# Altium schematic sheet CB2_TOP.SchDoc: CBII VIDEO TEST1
size A2; Engineer: SHOWELL; DocumentNumber: 1; Revision: 1.00; SheetNumber: 1; SheetTotal: 1; PageSetup: Record=PageOptions|CenterHorizontal=True|CenterVertical=True|PrintScale=1.47|XCorrection=1.00|YCorrection=1.00|PrintKind=0|BorderSize=5000000|LeftOffset=0|BottomOffset=0|Orientation=2|PaperLength=1000|PaperWidth=1000|Scale=100|PaperSource=7|PrintQuality=-4|MediaType=1|DitherType=10|PaperKind=A2|PrintScaleMode=1
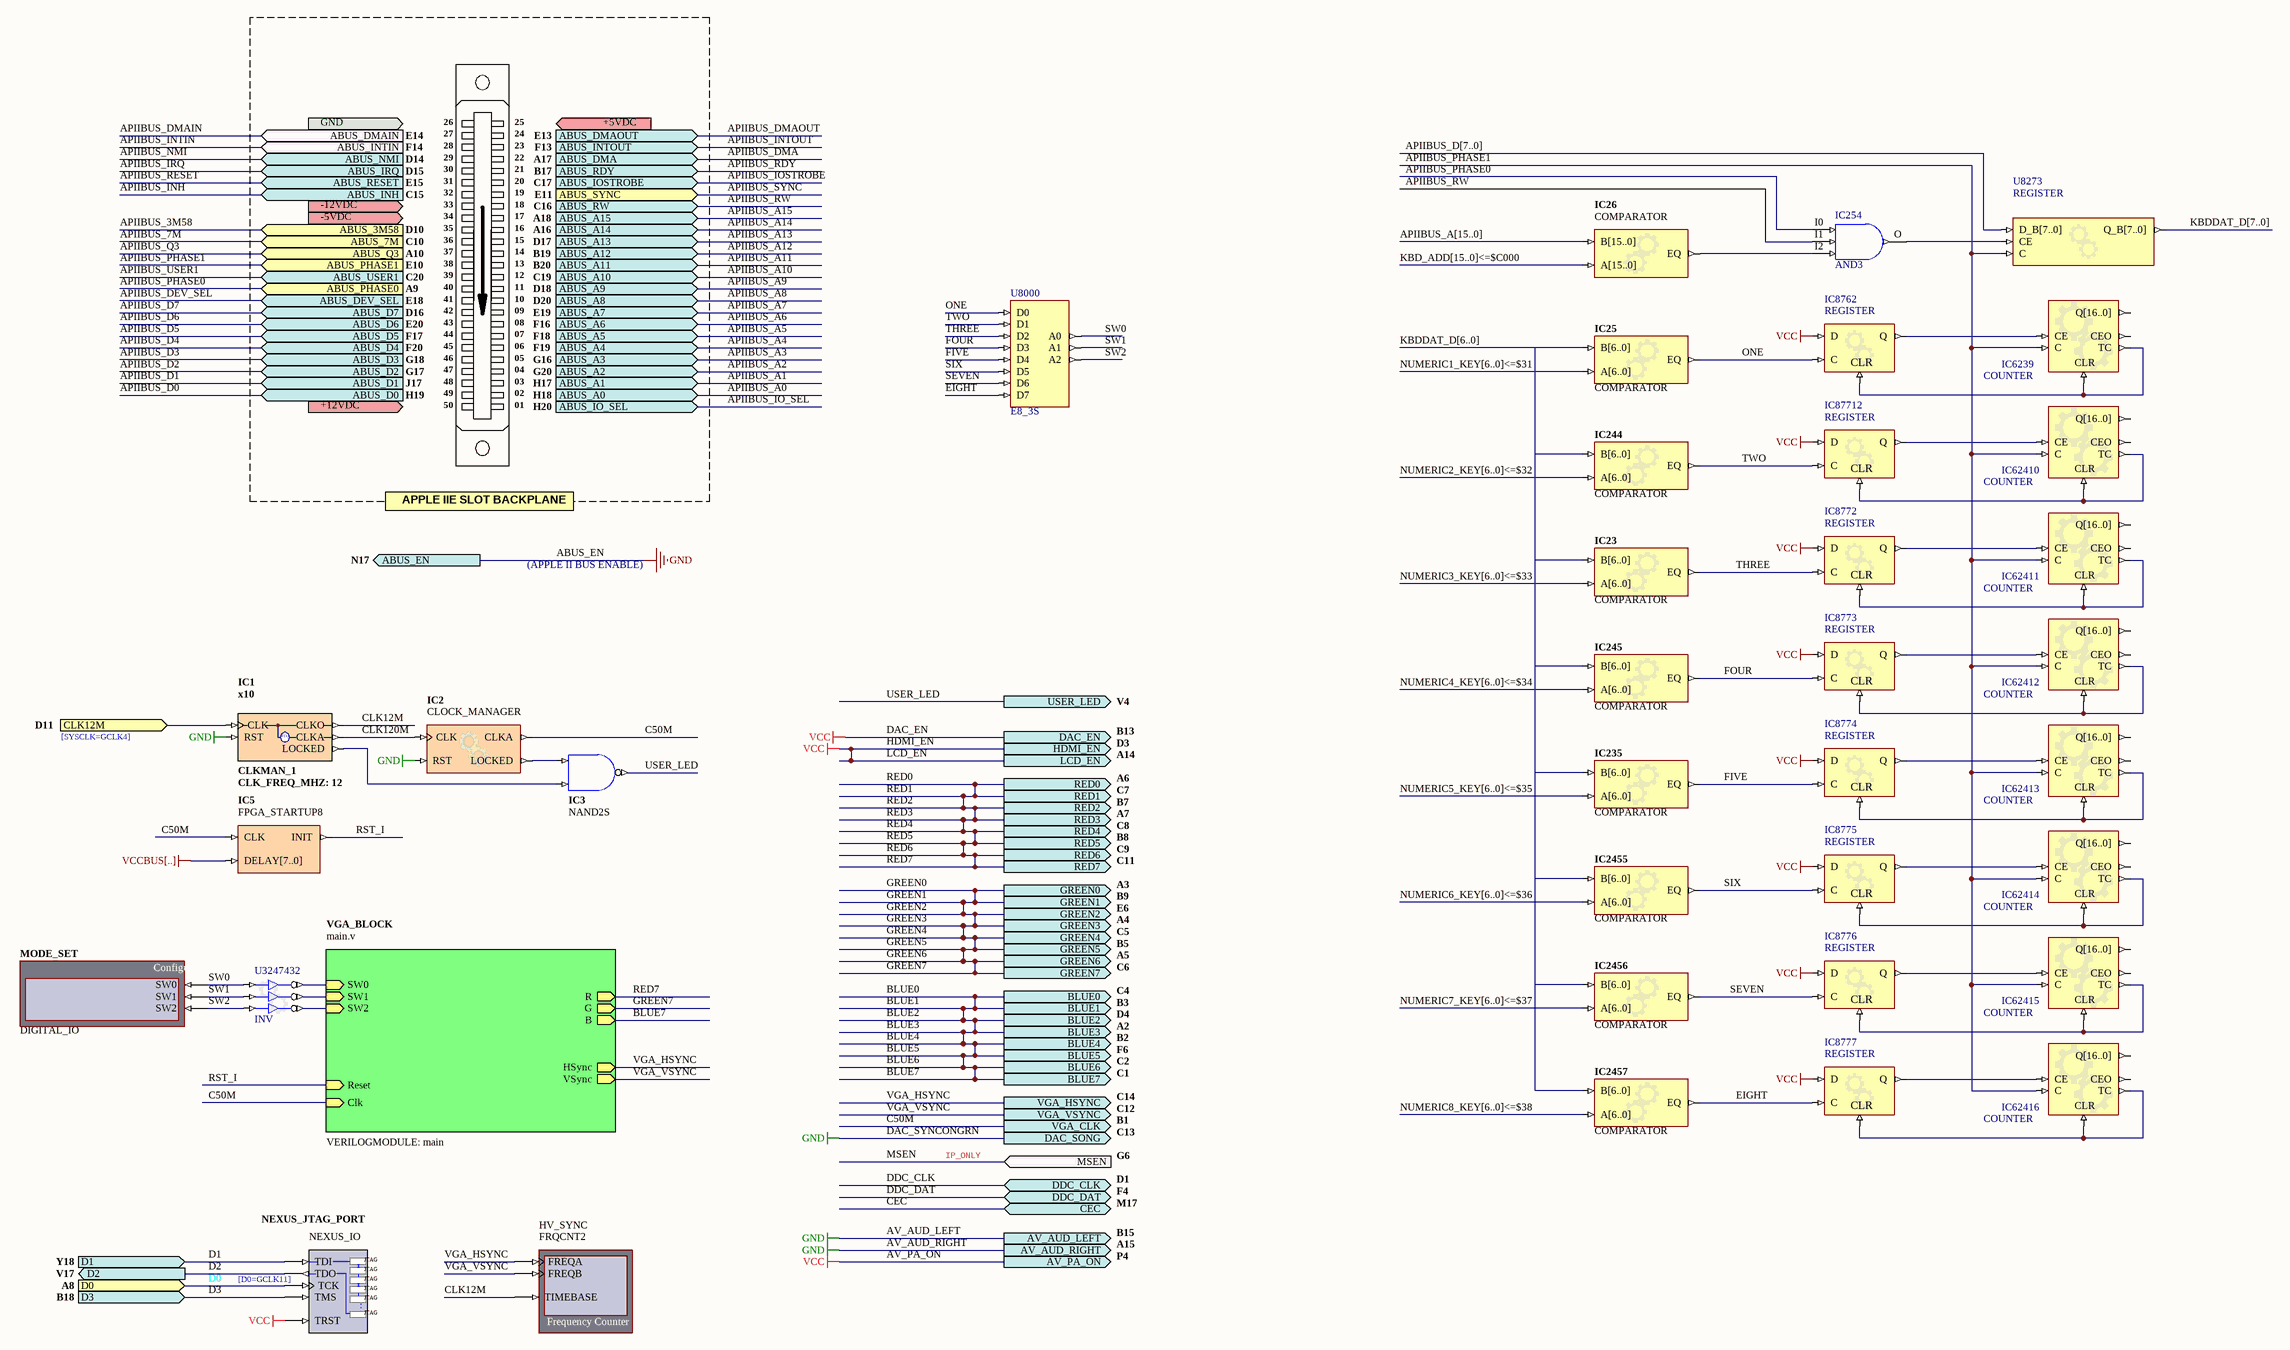
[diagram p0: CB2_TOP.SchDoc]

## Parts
HV_SYNC  FRQCNT2
IC1  CLKMAN_1  CLK_FREQ_MHZ: 12  ClkA_Operation: x10
IC2  CLOCK_MANAGER
IC3  NAND2S
IC5  FPGA_STARTUP8
IC23  COMPARATOR
IC25  COMPARATOR
IC26  COMPARATOR
IC235  COMPARATOR
IC244  COMPARATOR
IC245  COMPARATOR
IC254  AND3
IC2455  COMPARATOR
IC2456  COMPARATOR
IC2457  COMPARATOR
IC6239  COUNTER
IC8762  REGISTER
IC8772  REGISTER
IC8773  REGISTER
IC8774  REGISTER
IC8775  REGISTER
IC8776  REGISTER
IC8777  REGISTER
IC62410  COUNTER
IC62411  COUNTER
IC62412  COUNTER
IC62413  COUNTER
IC62414  COUNTER
IC62415  COUNTER
IC62416  COUNTER
IC87712  REGISTER
MODE_SET  DIGITAL_IO
NEXUS_JTAG_PORT  NEXUS_IO
U8000  E8_3S
U8273  REGISTER
U3247432  INV

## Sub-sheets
VGA_BLOCK = main.v: B (out), Clk (in), G (out), HSync (out), R (out), Reset (in), SW0 (in), SW1 (in), SW2 (in), VSync (out)  | VERILOGMODULE: main

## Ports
ABUS_3M58 (in, see D10), ABUS_7M (in, see C10), ABUS_A0 (in, see H18), ABUS_A1 (in, see H17), ABUS_A2 (in, see G20), ABUS_A3 (in, see G16), ABUS_A4 (in, see F19), ABUS_A5 (in, see F18), ABUS_A6 (in, see F16), ABUS_A7 (in, see E19), ABUS_A8 (in, see D20), ABUS_A9 (in, see D18), ABUS_A10 (in, see C19), ABUS_A11 (in, see B20), ABUS_A12 (in, see B19), ABUS_A13 (in, see D17), ABUS_A14 (in, see A16), ABUS_A15 (in, see A18), ABUS_D0 (in, see H19), ABUS_D1 (in, see J17), ABUS_D2 (in, see G17), ABUS_D3 (in, see G18), ABUS_D4 (in, see F20), ABUS_D5 (in, see F17), ABUS_D6 (in, see E20), ABUS_D7 (in, see D16), ABUS_DEV_SEL (in, see E18), ABUS_DMA (in, see A17), ABUS_DMAIN (in, see E14), ABUS_DMAOUT (in, see E13), ABUS_EN (out, see N17), ABUS_INH (in, see C15), ABUS_INTIN (in, see F14), ABUS_INTOUT (in, see F13), ABUS_IO_SEL (in, see H20), ABUS_IOSTROBE (in, see C17), ABUS_IRQ (in, see D15), ABUS_NMI (in, see D14), ABUS_PHASE0 (in, see A9), ABUS_PHASE1 (in, see E10), ABUS_Q3 (in, see A10), ABUS_RDY (in, see B17), ABUS_RESET (in, see E15), ABUS_RW (in, see C16), ABUS_SYNC (in, see E11), ABUS_USER1 (in, see C20), AV_AUD_LEFT (out, see B15), AV_AUD_RIGHT (out, see A15), AV_PA_ON (out, see P4), BLUE0 (out, see C4), BLUE1 (out, see B3), BLUE2 (out, see D4), BLUE3 (out, see A2), BLUE4 (out, see B2), BLUE5 (out, see F6), BLUE6 (out, see C2), BLUE7 (out, see C1), CEC (bidir, see M17), CLK12M (in, see D11), D0 (in, see A8), D1 (in, see Y18), D2 (out, see V17), D3 (in, see B18), DAC_EN (out, see B13), DAC_SONG (out, see C13), DDC_CLK (bidir, see D1), DDC_DAT (bidir, see F4), GREEN0 (out, see A3), GREEN1 (out, see B9), GREEN2 (out, see E6), GREEN3 (out, see A4), GREEN4 (out, see C5), GREEN5 (out, see B5), GREEN6 (out, see A5), GREEN7 (out, see C6), HDMI_EN (out, see D3), LCD_EN (out, see A14), MSEN (in, see G6), RED0 (out, see A6), RED1 (out, see C7), RED2 (out, see B7), RED3 (out, see A7), RED4 (out, see C8), RED5 (out, see B8), RED6 (out, see C9), RED7 (out, see C11), USER_LED (out, see V4), VGA_CLK (out, see B1), VGA_HSYNC (out, see C14), VGA_VSYNC (out, see C12)

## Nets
ABUS_EN: IC1.RST IC2.RST ; port DAC_SONG, port AV_AUD_LEFT, port AV_AUD_RIGHT, port ABUS_EN  [also labelled AV_AUD_LEFT, AV_AUD_RIGHT, DAC_SYNCONGRN, GND]
AV_PA_ON: IC8762.D IC8772.D IC8773.D IC8774.D IC8775.D IC8776.D IC8777.D IC87712.D NEXUS_JTAG_PORT.TRST ; port HDMI_EN, port AV_PA_ON, port DAC_EN, port LCD_EN  [also labelled DAC_EN, HDMI_EN, LCD_EN, VCC]
APIIBUS_PHASE0: IC254.I0 ; port ABUS_PHASE0
APIIBUS_PHASE1: IC6239.C IC62410.C IC62411.C IC62412.C IC62413.C IC62414.C IC62415.C IC62416.C U8273.C ; port ABUS_PHASE1
APIIBUS_RW: IC254.I1 ; port ABUS_RW
BLUE0: port BLUE2, port BLUE3, port BLUE4, port BLUE5, port BLUE6, port BLUE7, port BLUE0, port BLUE1, sheet VGA_BLOCK/B  [also labelled BLUE1, BLUE2, BLUE3, BLUE4, BLUE5, BLUE6, BLUE7]
C50M: IC2.CLKA IC5.CLK ; port VGA_CLK, sheet VGA_BLOCK/Clk
CLK12M: IC1.CLK ; port CLK12M
CLK12M: HV_SYNC.TIMEBASE IC1.CLKO  [a separate net that carries the same name]
CLK120M: IC1.CLKA IC2.CLK
D0: NEXUS_JTAG_PORT.TCK ; port D0
D1: NEXUS_JTAG_PORT.TDI ; port D1
D2: NEXUS_JTAG_PORT.TDO ; port D2
D3: NEXUS_JTAG_PORT.TMS ; port D3
EIGHT: IC2457.EQ IC8777.C U8000.D7
FIVE: IC235.EQ IC8774.C U8000.D4
FOUR: IC245.EQ IC8773.C U8000.D3
GREEN0: port GREEN2, port GREEN3, port GREEN4, port GREEN5, port GREEN6, port GREEN7, port GREEN0, port GREEN1, sheet VGA_BLOCK/G  [also labelled GREEN1, GREEN2, GREEN3, GREEN4, GREEN5, GREEN6, GREEN7]
ONE: IC25.EQ IC8762.C U8000.D0
RED0: port RED2, port RED3, port RED4, port RED5, port RED6, port RED7, port RED0, port RED1, sheet VGA_BLOCK/R  [also labelled RED1, RED2, RED3, RED4, RED5, RED6, RED7]
RST_I: IC5.INIT ; sheet VGA_BLOCK/Reset
SEVEN: IC2456.EQ IC8776.C U8000.D6
SIX: IC2455.EQ IC8775.C U8000.D5
SW0: MODE_SET.SW0 U8000.A0 U3247432.I0
SW1: MODE_SET.SW1 U8000.A1 U3247432.I1
SW2: MODE_SET.SW2 U8000.A2 U3247432.I2
THREE: IC23.EQ IC8772.C U8000.D2
TWO: IC244.EQ IC87712.C U8000.D1
USER_LED: IC3.O ; port USER_LED
VGA_HSYNC: HV_SYNC.FREQA ; port VGA_HSYNC, sheet VGA_BLOCK/HSync
VGA_VSYNC: HV_SYNC.FREQB ; port VGA_VSYNC, sheet VGA_BLOCK/VSync
NetIC1_LOCKED: IC1.LOCKED IC3.I1
NetIC2_LOCKED: IC2.LOCKED IC3.I0
NetIC26_EQ: IC26.EQ IC254.I2
NetIC254_O: IC254.O U8273.CE
NetIC6239_CE: IC6239.CE IC8762.Q
NetIC6239_CLR: IC6239.CLR IC6239.TC IC8762.CLR
NetIC8772_CLR: IC8772.CLR IC62411.CLR IC62411.TC
NetIC8772_Q: IC8772.Q IC62411.CE
NetIC8773_CLR: IC8773.CLR IC62412.CLR IC62412.TC
NetIC8773_Q: IC8773.Q IC62412.CE
NetIC8774_CLR: IC8774.CLR IC62413.CLR IC62413.TC
NetIC8774_Q: IC8774.Q IC62413.CE
NetIC8775_CLR: IC8775.CLR IC62414.CLR IC62414.TC
NetIC8775_Q: IC8775.Q IC62414.CE
NetIC8776_CLR: IC8776.CLR IC62415.CLR IC62415.TC
NetIC8776_Q: IC8776.Q IC62415.CE
NetIC8777_CLR: IC8777.CLR IC62416.CLR IC62416.TC
NetIC8777_Q: IC8777.Q IC62416.CE
NetIC62410_CE: IC62410.CE IC87712.Q
NetIC62410_CLR: IC62410.CLR IC62410.TC IC87712.CLR
NetU3247432_O0: U3247432.O0 ; sheet VGA_BLOCK/SW0
NetU3247432_O1: U3247432.O1 ; sheet VGA_BLOCK/SW1
NetU3247432_O2: U3247432.O2 ; sheet VGA_BLOCK/SW2

Not connected (* = marked no-connect by the designer): IC5 DELAY[7..0]; IC23 A[6..0] B[6..0]; IC25 A[6..0] B[6..0]; IC26 A[15..0] B[15..0]; IC235 A[6..0] B[6..0]; IC244 A[6..0] B[6..0]; IC245 A[6..0] B[6..0]; IC2455 A[6..0] B[6..0]; IC2456 A[6..0] B[6..0]; IC2457 A[6..0] B[6..0]; IC6239 CEO Q[16..0]; IC62410 CEO Q[16..0]; IC62411 CEO Q[16..0]; IC62412 CEO Q[16..0]; IC62413 CEO Q[16..0]; IC62414 CEO Q[16..0]; IC62415 CEO Q[16..0]; IC62416 CEO Q[16..0]; U8273 D_B[7..0] Q_B[7..0]

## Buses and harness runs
bus APIIBUS_A[15..0]
bus APIIBUS_D[7..0]
bus KBD_ADD[15..0]<=$C000
bus KBDDAT_D[6..0]
bus KBDDAT_D[7..0]
bus NUMERIC1_KEY[6..0]<=$31
bus NUMERIC2_KEY[6..0]<=$32
bus NUMERIC3_KEY[6..0]<=$33
bus NUMERIC4_KEY[6..0]<=$34
bus NUMERIC5_KEY[6..0]<=$35
bus NUMERIC6_KEY[6..0]<=$36
bus NUMERIC7_KEY[6..0]<=$37
bus NUMERIC8_KEY[6..0]<=$38

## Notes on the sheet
- GND
- 26
- 27
- 28
- 29
- 30
- 25
- 24
- 23
- 22
- 21
- +5VDC
- -12VDC
- -5VDC
- 31
- 32
- 33
- 34
- 35
- 20
- 19
- 18
- 17
- 16
- 36
- 37
- 38
- 39
- 40
- 15
- 14
- 13
- 12
- 11
- 41
- 42
- 43
- 44
- 45
- 10
- 09
- 08
- 07
- 06
- +12VDC
- 46
- 47
- 48
- 49
- 50
- 05
- 04
- 03
- 02
- 01
- APPLE IIE SLOT BACKPLANE
- (APPLE II BUS ENABLE)
- [SYSCLK=GCLK4]
- IP_ONLY
- (near NEXUS_JTAG_PORT) [D0=GCLK11]
- Labels drawn without touching a wire or pin: VCCBUS[..]

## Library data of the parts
HV_SYNC = FRQCNT2: Frequency Counter; NEXUS_CORE: Instrument; NEXUS_JTAG_DEVICE: True; NEXUS_JTAG_ORDER: 0
IC1 = CLKMAN_1: Single Operational Output Clock Manager; Clk_Count: 1
IC2 = CLOCKMANAGER: Configurable Clock Manager; ConfiguratorName: GENERIC_CLOCKMANAGER; ConfigurationParameters: {}Version[1.0]{}Option_Configuration[object _1: TClockManagerPersist / VersionMajor [ 0 / VersionMinor [ 0 / InputFreq [ 120.000000000000000000 / InputName [ 'CLK' / OutputTargets [ < / item / Name [ 'CLKA' / OutFreqMin [ 50.000000000000000000 / OutFreqMax [ 50.000000000000000000 / OutPostDivider [ 1.000000000000000000 / end> / OutputDevices [ < / item / Name [ 'Spartan3AN' / Valid [ True / OutputActuals [ < / item / Name [ 'CLK0' / Multipler [ 1.000000000000000000 / Divider [ 1.000000000000000000 / OutFreq [ 120.000000000000000000 / OutputMap [ 1 / end / item / Name [ 'CLK90' / Multipler [ 1.000000000000000000 / Divider [ 1.000000000000000000 / OutPhase [ 90.000000000000000000 / OutFreq [ 120.000000000000000000 / OutputMap [ 2 / end / item / Name [ 'CLK180' / Multipler [ 1.000000000000000000 / Divider [ 1.000000000000000000 / OutPhase [ 180.000000000000000000 / OutFreq [ 120.000000000000000000 / OutputMap [ 3 / end / item / Name [ 'CLK270' / Multipler [ 1.000000000000000000 / Divider [ 1.000000000000000000 / OutPhase [ 270.000000000000000000 / OutFreq [ 120.000000000000000000 / OutputMap [ 4 / end / item / Name [ 'CLK2X' / Multipler [ 2.000000000000000000 / Divider [ 1.000000000000000000 / OutFreq [ 240.000000000000000000 / OutputMap [ 5 / end / item / Name [ 'CLKDV' / Multipler [ 1.000000000000000000 / Divider [ 16.000000000000000000 / OutFreq [ 7.500000000000000000 / OutputMap [ 6 / end / item / Name [ 'CLK2X180' / Multipler [ 1.000000000000000000 / Divider [ 1.000000000000000000 / OutPhase [ 180.000000000000000000 / OutFreq [ 240.000000000000000000 / OutputMap [ 7 / end / item / Name [ 'CLKFX' / Multipler [ 5.000000000000000000 / Divider [ 12.000000000000000000 / OutFreq [ 50.000000000000000000 / OutputMap [ 0 / end / item / Name [ 'CLKFX180' / Multipler [ 1.000000000000000000 / Divider [ 1.000000000000000000 / OutPhase [ 180.000000000000000000 / OutFreq [ 50.000000000000000000 / OutputMap [ 8 / end> / InternalActuals [ <> / CustomVars [ <> / end> / MinInputFreq [ 1.000000000000000000 / MaxInputFreq [ 280.000000000000000000 / MinOutputFreq [ 18.000000000000000000 / MaxOutputFreq [ 210.000000000000000000 / MaxOutputCount [ 9 / end]{}
IC3 = NAND2S: 2-Input NAND Gate, Single Pin Version; XilinxEquivalent: NAND2; FunctionalClass: Logic Primitive; PortSize: 2; ArchiveName: GENERIC; VHDLIB_SIM: GENERIC_LIB
IC5 = FPGA_STARTUP8: FPGA Startup With 8 Bit Delay
IC23 IC25 IC235 IC244 IC245 IC2455-IC2457 = COMPARATOR: Configurable Comparator; ConfiguratorName: GENERIC_COMPARATOR; ConfigurationParameters: {}Version[1.0]{}EQ[True]{}GT[False]{}LT[False]{}SignalWidth[7]{}BusInputs[True]{}RegisterOutputs[False]{}NegClockEdge[False]{}
IC26 = COMPARATOR: Configurable Comparator; ConfiguratorName: GENERIC_COMPARATOR; ConfigurationParameters: {}Version[1.0]{}EQ[True]{}GT[False]{}LT[False]{}SignalWidth[16]{}BusInputs[True]{}RegisterOutputs[False]{}NegClockEdge[False]{}
IC254 = AND3: 3-Input AND Gate; FPGAVendor: Xilinx
IC6239 IC62410-IC62416 = COUNTER: Configurable Counter; ConfiguratorName: GENERIC_COUNTER; ConfigurationParameters: {}Version[1.0]{}Type[Binary]{}SyncReset[False]{}NegativeClockEdge[False]{}FixedDirection[True]{}IsIncrement[True]{}SignalWidth[17]{}MaxValue[100000]{}BusOutput[True]{}Loadable[False]{}BusInput[False]{}
IC8762 IC8772-IC8777 IC87712 = REGISTER: Configurable Register; ConfiguratorName: GENERIC_REGISTER; ConfigurationParameters: {}Version[1.1]{}RegisterType[DFlipFlop]{}NegativeTrigger[False]{}TriggerEnable[False]{}ResetMode[Asynchronous]{}SetMode[None]{}SignalCount[1]{}SignalWidth0[1]{}OutputOption0[Normal]{}
MODE_SET = DIGITAL_IO: Configurable Digital IO; NEXUS_CORE: Instrument; NEXUS_JTAG_DEVICE: True; NEXUS_JTAG_ORDER: 0; ConfigurationParameters: {}Version[2.0]{}StorageType[3]{}InterfaceType[Parallel]{}SchCompWidth[140]{}Input0Name[SW0]{}Input0Width[1]{}Input0InitValue[0]{}Input0Kind[Numeric]{}Input0NumRadix[Binary]{}Input1Name[SW1]{}Input1Width[1]{}Input1InitValue[0]{}Input1Kind[Numeric]{}Input1NumRadix[Binary]{}Input2Name[SW2]{}Input2Width[1]{}Input2InitValue[0]{}Input2Kind[Numeric]{}Input2NumRadix[Binary]{}NoOutputs[ ]{}Designator[MODE_SET]{}InternalID[1]{}
NEXUS_JTAG_PORT = NEXUS_JTAG_PORT: Soft Nexus-Chain Connector; NEXUS_JTAG_CONNECTOR: True
U8000 = E8_3S: 8- to 3-Bit Priority Encoder, Single Pin Version; SubClass: n_m; PortSize: 3; ArchiveName: GENERIC; VHDLIB_SIM: GENERIC_LIB
U8273 = REGISTER: Configurable Register; ConfiguratorName: GENERIC_REGISTER; ConfigurationParameters: {}Version[1.1]{}RegisterType[DFlipFlop]{}NegativeTrigger[False]{}TriggerEnable[True]{}ResetMode[None]{}SetMode[None]{}SignalCount[1]{}SignalWidth0[8]{}OutputOption0[Normal]{}
U3247432 = INV: Configurable Inverter; ConfigurationParameters: {}Version[1.1]{}SignalCount[3]{}SignalWidth0[1]{}OutputOption0[Inverted]{}SignalWidth1[1]{}OutputOption1[Inverted]{}SignalWidth2[1]{}OutputOption2[Inverted]{}EnableMode[None]{}ShowPinNames[False]{}; ConfiguratorName: GENERIC_BUFFER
